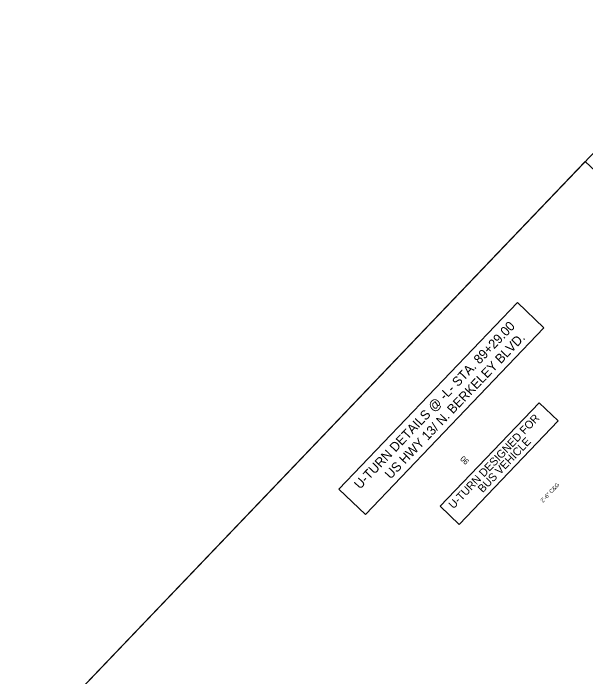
# Model space of a CAD drawing. Extents: x 2326836 to 2328631, y 602012 to 603789.
# Drawn here: x 2326836 to 2327551, y 602841 to 603670 of the extents above; entities that cross this region are included whole.
import ezdxf

# ---------------------------------------------------------------- set-up
doc = ezdxf.new("R2010")
doc.units = 0
for name, color, linetype in [('Default', 7, 'Continuous'), ('Prop Dimension Text', 7, 'Continuous'), ('Prop Horizontal Alignment Tick Label', 7, 'Continuous'), ('Scratch_Level_1', 7, 'Continuous'), ('Sheet Plan CELL', 7, 'Continuous')]:
    doc.layers.add(name, color=color, linetype=linetype)

msp = doc.modelspace()

# ---------------------------------------------------------------- linework, layer by layer
at = {"layer": 'Default'}
for points in [[(2327242.72, 603075.78), (2327465.59, 603309.02), (2327498.72, 603277.35), (2327275.86, 603044.11)], [(2327392.79, 603031.67), (2327516.47, 603161.12), (2327492.78, 603183.75), (2327369.1, 603054.3)]]:
    msp.add_lwpolyline(points, close=True, dxfattribs=at)
at = {"layer": 'Scratch_Level_1'}
msp.add_lwpolyline([(2326885.09, 602788.9), (2327620.52, 603558.61), (2327714.85, 603468.48), (2327770.17, 603526.38), (2328049.95, 603259.07), (2327259.2, 602431.46)], close=True, dxfattribs=at)
at = {"layer": 'Sheet Plan CELL'}
msp.add_lwpolyline([(2326835.98, 602737.58), (2327550.28, 603485.23), (2327577.17, 603459.54), (2327678.48, 603565.59), (2327746, 603501.08), (2327828.41, 603587.34), (2327892.92, 603525.71), (2328031.11, 603670.36), (2328251.83, 603459.46), (2327215.55, 602374.93)], close=True, dxfattribs=at)

# ---------------------------------------------------------------- texts
at = {"layer": 'Default'}
for s, height, rotation, p in [('U-TURN DETAILS @ -L- STA. 89+29.00', 11.6664, 46.30318, (2327268.94, 603074.92)), ('US HWY 13/ N. BERKELEY BLVD.', 11.6664, 46.30318, (2327307.2, 603087.52)), ('U-TURN DESIGNED FOR ', 10, 46.3051, (2327385.77, 603050.42)), ('BUS VEHICLE', 10, 46.3051, (2327422.31, 603070.56))]:
    msp.add_text(s, height=height, rotation=rotation, dxfattribs=at).set_placement(p)
at = {"layer": 'Prop Dimension Text'}
msp.add_text('2\'-6" C&G', height=5, rotation=46.52652, dxfattribs=at).set_placement((2327497.46, 603058.59))
msp.add_text('2\'-6" C&G', height=5, rotation=46.52652, dxfattribs=at).set_placement((2327497.46, 603058.59))
at = {"layer": 'Prop Horizontal Alignment Tick Label'}
msp.add_text('90', height=7, rotation=136.52652, dxfattribs=at).set_placement((2327405.8, 603110.73))

doc.saveas('drawing.dxf')
